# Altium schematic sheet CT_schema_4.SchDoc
size 293 x 134 mm
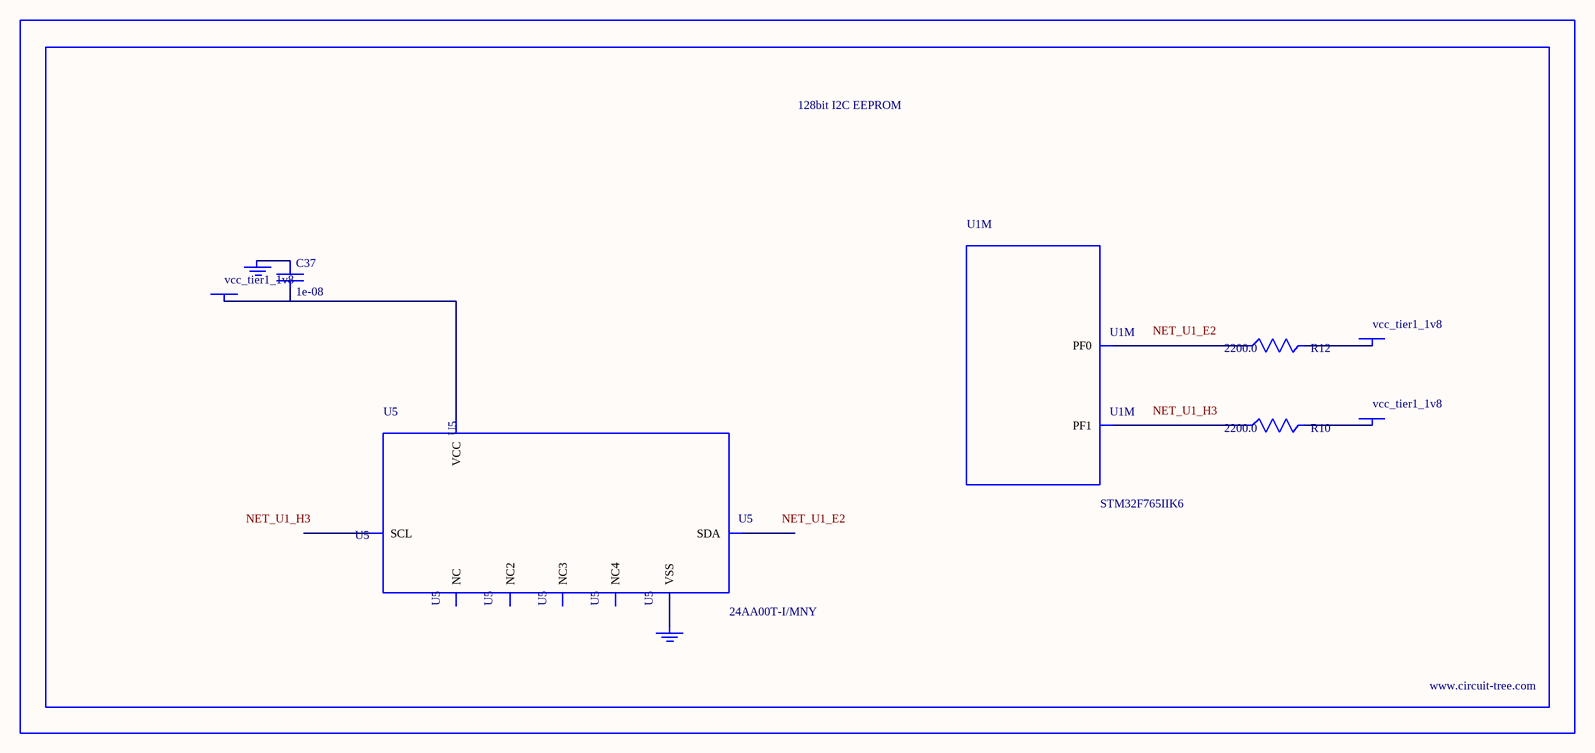
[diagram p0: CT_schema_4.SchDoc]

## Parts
BORDER3  (no value)
C37  1e-08  [C0402]
GND_INSTANCE_3_0  (no value)
GND_INSTANCE_3_1  (no value)
POWER_INSTANCE_3_0  vcc_tier1_1v8
POWER_INSTANCE_3_1  vcc_tier1_1v8
POWER_INSTANCE_3_2  vcc_tier1_1v8
R10  2200.0  [R0603]
R12  2200.0  [R0603]
U1  STM32F765IIK6  [UFBGA176_25]  (part M of 17)
U5  24AA00T-I/MNY  [TDFN-8/6MM]

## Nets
NetC37_1: C37.1 GND_INSTANCE_3_0.0(GND)
NetC37_2: C37.2 POWER_INSTANCE_3_0.0(PWR) U5.8(VCC)
NetGND_INSTANCE_3_1_0: GND_INSTANCE_3_1.0(GND) U5.4(VSS)
NetPOWER_INSTANCE_3_1_0: POWER_INSTANCE_3_1.0(PWR) R12.2
NetPOWER_INSTANCE_3_2_0: POWER_INSTANCE_3_2.0(PWR) R10.2
NetR10_1: R10.1 U1.H3(PF1)
NetR12_1: R12.1 U1.E2(PF0)

Not connected (* = marked no-connect by the designer): U5 1(NC) 2(NC2) 3(NC3) 5(SDA) 6(SCL) 7(NC4)

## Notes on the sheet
- Labels drawn without touching a wire or pin: NET_U1_E2, NET_U1_H3

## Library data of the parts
BORDER3 = BORDER_PAGE3
C37 = C0402C103K3RAC
GND_INSTANCE_3_0 GND_INSTANCE_3_1 = GND
POWER_INSTANCE_3_0-POWER_INSTANCE_3_2 = PWR
R10 R12 = RC0603JR-072K2L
